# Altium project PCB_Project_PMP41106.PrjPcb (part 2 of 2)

## Sheet PCB_Project_PMP41106_CoverSheet.SchDoc
size 431 x 279 mm; Date: Not shown in title block; ApprovedBy: Not shown in title block; CheckedBy: Not shown in title block; Author: Not shown in title block; CompanyName: Not shown in title block; Engineer: Not shown in title block; Organization: Not shown in title block; Address1: Not shown in title block; Address2: Not shown in title block; Address3: Not shown in title block; Address4: Not shown in title block; DocumentNumber: 1; Revision: Use project parameter SCH_Rev; SheetNumber: 1; SheetTotal: 3; PageSetup: Record=PageOptions¦CenterHorizontal=True¦CenterVertical=True¦PrintScale=1.00¦XCorrection=1.00¦YCorrection=1.00¦PrintKind=0¦BorderSize=5000000¦LeftOffset=0¦BottomOffset=0¦Orientation=2¦PaperLength=1000¦PaperWidth=1000¦Scale=100¦PaperSource=15¦PrintQuality=600¦MediaType=1¦DitherType=10¦PaperKind=Letter¦PrintScaleMode=1
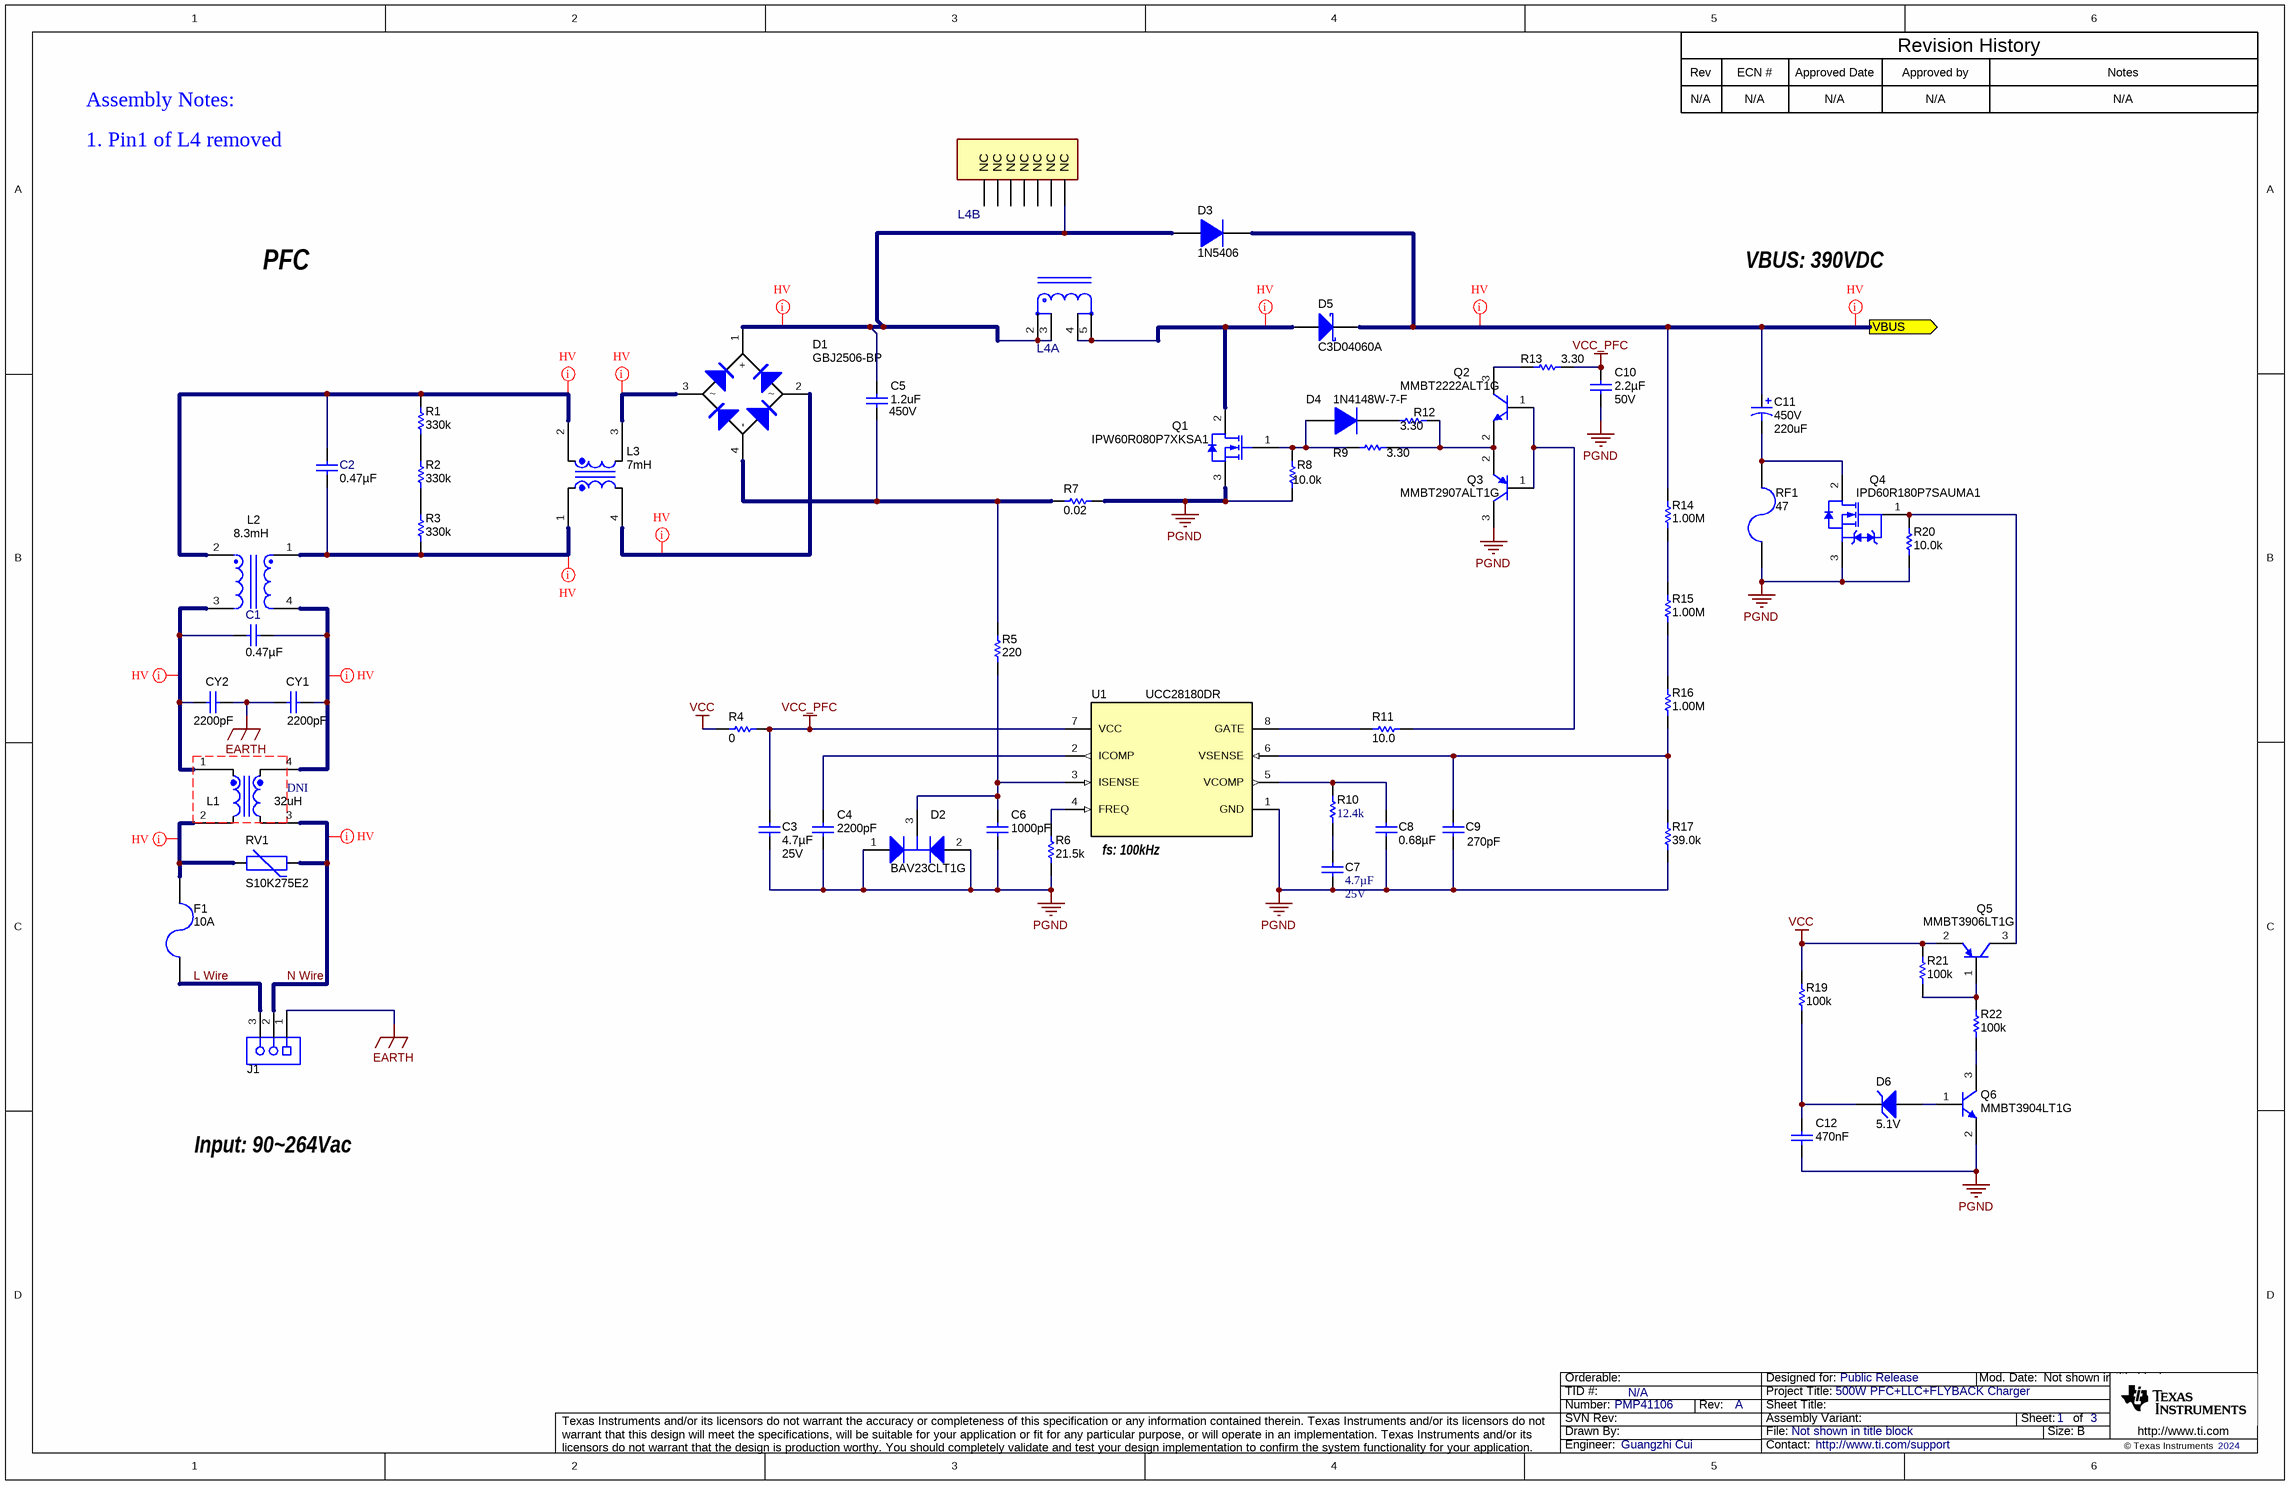
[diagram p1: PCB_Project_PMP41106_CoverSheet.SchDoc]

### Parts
C1  ValueDisplayed: 0.47µF  [Kemet_1800x850x1450]  (hidden comment: R46KI347050P0K)
C2  ValueDisplayed: 0.47µF  [Kemet_1800x850x1450]  (hidden comment: R46KI347050P0K)
C3  Cap_F: 4.7µF  VDC_V: 25V  [0805_HV]  (hidden comment: C2012X7R1E475K125AB)
C4  ValueDisplayed: 2200pF  [0603]  (hidden comment: GRM1885C1H222JA01D)
C5  VDC_V: 450V  ValueDisplayed: 1.2uF  [B32922_17.5mm]  (hidden comment: ECW-FD2W125K)
C6  ValueDisplayed: 1000pF  [0603]  (hidden comment: GRM1885C1H102FA01J)
C7  Cap_F: 4.7µF  VDC_V: 25V  [0805_150]  (hidden comment: 08053C225KAT2A)
C8  Cap_F: 0.68µF  [0603]  (hidden comment: C0603C105K3RACTU)
C9  ValueDisplayed: 270pF  [0603]  (hidden comment: GRM1885C1H271JA01D)
C10  Cap_F: 2.2µF  VDC_V: 50V  [0805_HV]  (hidden comment: C2012X7R1H225K125AC)
C11  VDC_V: 450V  ValueDisplayed: 220uF  [HXG_2500x4000]  (hidden comment: 450HXG220MEFCSN25X40)
C12  Cap_F: 470nF  [0603]  (hidden comment: GRM188R71E474KA12D)
CY1  ValueDisplayed: 2200pF  [E_900x700x900]  (hidden comment: DE6E3KJ222MN3A)
CY2  ValueDisplayed: 2200pF  [E_900x700x900]  (hidden comment: DE6E3KJ222MN3A)
D1  GBJ2506-BP  [GBJ]
D2  BAV23CLT1G  [SOT-23]
D3  1N5406  [DO-201AD]
D4  1N4148W-7-F  [SOD-123]
D5  C3D04060A  [TO-220-F2]
D6  value 5.1V  [SOD-323]  (hidden comment: MM3Z5V1ST1G)
F1  Irating_A: 10A  [FUSE_0216]  (hidden comment: 0216010.MXEP)
J1  1714968  [Phoenix_1714968]  (value not drawn)
L1  value 32uH  [WE-CMB_NiZn_S]  (hidden comment: 744842932)
L2  Ind_H: 8.3mH  [FP-YXBCM020013007C_PTH_CHOKE_12MM5_25MM0-MFG]  (hidden comment: YXBCM020013007C)
L3  value 7mH  [WE-CMBNC_L]  (hidden comment: 7448040707)
L4  MAG-3001497  [FP-MAG-3001497_PTH12-MFG]  (value not drawn)  (parts A,B of 2)
Q1  IPW60R080P7XKSA1  [TO-247]
Q2  MMBT2222ALT1G  [SOT-23]
Q3  MMBT2907ALT1G  [SOT-23]
Q4  IPD60R180P7SAUMA1  [DPAK]
Q5  MMBT3906LT1G  [SOT-23]
Q6  MMBT3904LT1G  [SOT-23]
R1  ValueDisplayed: 330k  [1206]  (hidden comment: RC1206FR-07330KL)
R2  ValueDisplayed: 330k  [1206]  (hidden comment: RC1206FR-07330KL)
R3  ValueDisplayed: 330k  [1206]  (hidden comment: RC1206FR-07330KL)
R4  ValueDisplayed: 0  [1206]  (hidden comment: RC1206JR-070RL)
R5  ValueDisplayed: 220  [0603]  (hidden comment: RC0603FR-07220RL)
R6  ValueDisplayed: 21.5k  [0603]  (hidden comment: RC0603FR-0721K5L)
R7  ValueDisplayed: 0.02  [2512]  (hidden comment: CSRN2512FK20L0)
R8  ValueDisplayed: 10.0k  [0603]  (hidden comment: RC0603FR-0710KL)
R9  ValueDisplayed: 3.30  [1206]  (hidden comment: RC1206FR-073R3L)
R10  ValueDisplayed: 12.4k  [0603]  (hidden comment: RC0603FR-0711K5L)
R11  ValueDisplayed: 10.0  [0603]  (hidden comment: RC0603FR-0710RL)
R12  ValueDisplayed: 3.30  [1206]  (hidden comment: RC1206FR-073R3L)
R13  ValueDisplayed: 3.30  [1206]  (hidden comment: RC1206FR-073R3L)
R14  ValueDisplayed: 1.00M  [1206]  (hidden comment: RC1206FR-071ML)
R15  ValueDisplayed: 1.00M  [1206]  (hidden comment: RC1206FR-071ML)
R16  ValueDisplayed: 1.00M  [1206]  (hidden comment: RC1206FR-071ML)
R17  ValueDisplayed: 39.0k  [0603]  (hidden comment: RC0603FR-0739KL)
R19  ValueDisplayed: 100k  [0603]  (hidden comment: RC0603FR-07100KL)
R20  ValueDisplayed: 10.0k  [0603]  (hidden comment: RC0603FR-0710KL)
R21  ValueDisplayed: 100k  [0603]  (hidden comment: RC0603FR-07100KL)
R22  ValueDisplayed: 100k  [0603]  (hidden comment: RC0603FR-07100KL)
RF1  ValueDisplayed: 47  [EMC2]  (hidden comment: EMC2-47RKI)
RV1  S10K275E2  [VAR_S10K275E2]
U1  UCC28180DR  [D0008A_N]

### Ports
VBUS (out)

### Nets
EARTH: CY1.1 CY2.2 J1.1
PGND: C3.2 C4.2 C6.2 C7.2 C8.2 C9.2 C10.2 C12.2 D2.1(A) D2.2(K) Q1.3(S) Q3.3(C) Q4.3(S) Q6.2(E) R6.1 R7.2 R8.1 R17.1 R20.1 RF1.2 U1.1(GND)
VCC: Q5.2(E) R4.1 R19.2 R21.2
VCC_PFC: C3.1 C10.1 R4.2 R13.1 U1.7(VCC)
L Wire: F1.2 J1.3
N Wire: J1.2 L1.3 RV1.2
VBUS: C11.1(+) D3.1(K) D5.1(K) R14.2 ; port VBUS
NetC1_1: C1.1 CY2.1 L1.1 L2.3
NetC1_2: C1.2 CY1.2 L1.4 L2.4
NetC2_1: C2.1 L2.1 L3.1 R3.1
NetC2_2: C2.2 L2.2 L3.2 R1.2
NetC4_1: C4.1 U1.2(ICOMP)
NetC5_1: C5.1 D1.1(+) D3.2(A) L4.1(NC) L4.2 L4.3
NetC5_2: C5.2 D1.4(-) R5.2 R7.1
NetC6_1: C6.1 D2.3(C) R5.1 U1.3(ISENSE)
NetC7_1: C7.1 R10.1
NetC8_1: C8.1 R10.2 U1.5(VCOMP)
NetC9_1: C9.1 R16.1 R17.2 U1.6(VSENSE)
NetC11_2: C11.2(-) Q4.2(D) RF1.1
NetC12_1: C12.1 D6.1(K) R19.1
NetD1_2: D1.2 L3.4
NetD1_3: D1.3 L3.3
NetD4_1: D4.1(K) R12.2
NetD4_2: D4.2(A) Q1.1(G) R8.2 R9.2
NetD5_2: D5.2(A) L4.4 L4.5 Q1.2(D)
NetD6_2: D6.2(A) Q6.1(B)
NetF1_1: F1.1 L1.2 RV1.1
NetQ2_1: Q2.1(B) Q3.1(B) R11.2
NetQ2_2: Q2.2(E) Q3.2(E) R9.1 R12.1
NetQ2_3: Q2.3(C) R13.2
NetQ4_1: Q4.1(G) Q5.3(C) R20.2
NetQ5_1: Q5.1(B) R21.1 R22.2
NetQ6_3: Q6.3(C) R22.1
NetR1_1: R1.1 R2.2
NetR2_1: R2.1 R3.2
NetR6_2: R6.2 U1.4(FREQ)
NetR11_1: R11.1 U1.8(GATE)
NetR14_1: R14.1 R15.2
NetR15_1: R15.1 R16.2

Not connected (* = marked no-connect by the designer): L4 7(NC) 8(NC) 9(NC) 10(NC) 11(NC) 12(NC)

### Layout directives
net class HV: N Wire, NetC1_1, NetC1_2, NetC2_1, NetC2_2, NetC5_1, NetD1_2, NetD1_3, NetD5_2, NetF1_1, VBUS

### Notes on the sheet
- Rev
- N/A
- ECN #
- Approved Date
- Approved by
- Revision History
- Notes
- Assembly Notes:
- 1. Pin1 of L4 removed
- PFC
- VBUS: 390VDC
- (near L1) DNI
- fs: 100kHz
- Input: 90|64Vac

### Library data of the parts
C1 C2 = CMP-0078590-1: CAP, Film, 0.47 µF, X2 275 VAC, +/- 10%, TH; Manufacturer: Kemet; Cap_F: 470nF; SizeAreaWB_mm2: 210; VAC_X: 275; SizeArea_mm2: 153; AEC Qualified: N; AEC Category: Q200; Value: 0.47uF; TaMax_C: 110°C; SizeZ_mm: 14.6; TaMin_C: -40°C; SizeY_mm: 8.5; CompType: Capacitor; SizeX_mm: 18; Cap_Case: 18x8.5x14.5
C3 = CMP-0007870-2: CAP, CERM, 4.7 uF, 25 V, +/- 10%, X7R, 0805; Manufacturer: TDK; TaMin_C: -55°C; Polarized: N; SizeAreaWB_mm2: 6.75; Value1: Unknown; U/M: EA; Value: 4.7uF; TaMax_C: 125°C; SizeZ_mm: 1.45; SizeX_mm: 2; SizeY_mm: 1.25; Cap_Case: 0805; SizeArea_mm2: 2.5; AEC Category: Q200
C4 = CMP-0007198-4: CAP, CERM, 2200 pF, 50 V, +/- 5%, C0G/NP0, 0603; Manufacturer: MuRata; TaMin_C: -55°C; Polarized: N; SizeAreaWB_mm2: 4.68; Value1: Unknown; U/M: EA; Value: 2200pF; TaMax_C: 125°C; SizeZ_mm: 1; SizeX_mm: 1.6; SizeY_mm: 0.8; Value2: 50V; SizeArea_mm2: 1.28; CompType: Capacitor; Cap_F: 2.2nF; AEC Category: Q200
C5 = CMP-0012412-3: CAP, Film, 1.2 uF, 450 V, +/- 10%, TH; Manufacturer: Panasonic Electronic Components; Polarized: N; SizeAreaWB_mm2: 220; Value1: Unknown; Value: 1.2uF; TaMax_C: 110°C; SizeZ_mm: 17.5; SizeX_mm: 18; SizeY_mm: 9; SizeArea_mm2: 162; CompType: Capacitor; Cap_F: 470nF; AEC Category: Q200
C6 = CMP-0007172-4: CAP, CERM, 1000 pF, 50 V, +/- 1%, C0G/NP0, 0603; Manufacturer: MuRata; TaMin_C: -55°C; Polarized: N; SizeAreaWB_mm2: 4.68; Value1: Unknown; U/M: EA; Value: 1000pF; TaMax_C: 125°C; SizeZ_mm: 1; SizeX_mm: 1.6; SizeY_mm: 0.8; Value2: 50V; SizeArea_mm2: 1.28; CompType: Capacitor; Cap_F: 1nF; AEC Category: Q200
C7 = CMP-0007870-2: CAP, CERM, 4.7 uF, 25 V, +/- 10%, X7R, 0805; Manufacturer: TDK; PartNumber: C2012X7R1E475K125AB; TaMin_C: -55°C; Polarized: N; SizeAreaWB_mm2: 6.75; Value1: Unknown; U/M: EA; Value: 4.7uF; TaMax_C: 125°C; SizeZ_mm: 1.45; SizeX_mm: 2; SizeY_mm: 1.25; Cap_Case: 0805; SizeArea_mm2: 2.5; AEC Category: Q200
C8 = CMP-0006867-4: CAP, CERM, 0.68uF, 25 V, +/- 10%, X7R, 0603; Manufacturer: Kemet; TaMin_C: -55°C; Polarized: N; SizeAreaWB_mm2: 4.68; Value1: Unknown; U/M: EA; TaMax_C: 125°C; SizeZ_mm: 1; SizeX_mm: 1.6; SizeY_mm: 0.8; Value2: 25V; SizeArea_mm2: 1.28; CompType: Capacitor; AEC Category: Q200; ValueDisplayed: 1uF
C9 = CMP-0007203-4: CAP, CERM, 270 pF, 50 V, +/- 5%, C0G/NP0, 0603; Manufacturer: MuRata; TaMin_C: -55°C; Polarized: N; SizeAreaWB_mm2: 4.68; Value1: Unknown; U/M: EA; Value: 270pF; TaMax_C: 125°C; SizeZ_mm: 1; SizeX_mm: 1.6; SizeY_mm: 0.8; Value2: 50V; SizeArea_mm2: 1.28; CompType: Capacitor; AEC Category: Q200
C10 = CMP-0007877-2: CAP, CERM, 2.2 uF, 50 V, +/- 10%, X7R, 0805; Manufacturer: TDK; TaMin_C: -55°C; ESR_ohm: 3.66m; Polarized: N; SizeAreaWB_mm2: 6.75; Value1: 0.00366 ohm; U/M: EA; Value: 2.2uF; TaMax_C: 125°C; SizeZ_mm: 1.45; SizeX_mm: 2; SizeY_mm: 1.25; Cap_Case: 0805; SizeArea_mm2: 2.5; IRMS_A: 3.41207A; AEC Category: Q200
C11 = CMP-0009979-2: CAP, AL, 220 uF, 450 V, +/- 20%, TH; Manufacturer: Rubycon; TaMin_C: -25°C; Polarized: Y; SizeAreaWB_mm2: 729; Value1: Unknown; U/M: EA; Value: 220uF; TaMax_C: 105°C; SizeZ_mm: 42; SizeX_mm: 25; Cap_Case: 25x40mm; SizeArea_mm2: 625; CompType: Capacitor; AEC Qualified: N; Cap_F: 220µF; IRMS_A: 1.97A; AEC Category: Q200
C12 = CMP-0007424-4: CAP, CERM, 0.47 uF, 25 V, +/- 10%, X7R, 0603; Manufacturer: MuRata; TaMin_C: -55°C; Polarized: N; SizeAreaWB_mm2: 4.68; Value1: Unknown; U/M: EA; Value: 0.47uF; TaMax_C: 125°C; SizeZ_mm: 1; SizeX_mm: 1.6; SizeY_mm: 0.8; Value2: 25V; SizeArea_mm2: 1.28; CompType: Capacitor; AEC Category: Q200
CY1 CY2 = DE6E3KJ222MN3A: CAP, CERM, 2200 pF, 300 V, +/- 20%, E, TH, 2- Leads, Body 9x7mm, Pin Spacing 7.5mm; Manufacturer: MuRata; Polarized: N; CompType: Capacitor; Value: 2200pF; U/M: EA; Cap_F: 0.0000000022; Tolerance_%: 20; Value1: Unknown; VDC_V: 300; Value2: 300V; TaMin_C: -40; TaMax_C: 125; Cap_Case: 9x7x9mm; SizeArea_mm2: 63; SizeAreaWB_mm2: 99; SizeX_mm: 9; SizeY_mm: 7; SizeZ_mm: 12; AEC Category: Q200
D1 = CMP-0082068-2: Diode, P-N-Bridge, 600 V, 25 A, TH; Manufacturer: Micro Commercial Components; AEC Category: Q101; Io_A: 25A; SizeY_mm: 4.6; AEC Qualified: N; SizeZ_mm: 24; Vr_V: 600V; SizeAreaWB_mm2: 211.2; Value: 600V; SizeX_mm: 30; TJmax_C: 150°C; Vf_V: 1.05V; RJC_CperW: 0.6; SizeArea_mm2: 138
D2 = CMP-0029178-2: Diode, Switching, 250 V, 0.4 A, SOT-23; Manufacturer: ON Semiconductor; Value2: 1.25V; SizeArea_mm2: 7.5; SizeAreaWB_mm2: 14; Green_Lifecycle: Not Set; Green_REACh: Incomplete; Io_A: 4dA; Vr_V: 250V; SizeZ_mm: 1.1; Value1: 0.4A; Value: 250V; SizeY_mm: 3; SizeX_mm: 2.5; TJmax_C: 150°C; AEC Category: Q101; AEC Qualified: N
D3 = CMP-0029223-3: Diode, Switching-Bridge, 600 V, 3 A, TH; Manufacturer: Vishay-Semiconductor; SizeArea_mm2: 109.08; Value1: 3A; Green_Lifecycle: Not Set; Green_REACh: Incomplete; AEC Category: Q101; Vr_V: 600V; Value: 600V; Value2: 1.2V; SizeAreaWB_mm2: 166.38; SizeX_mm: 21.6; SizeY_mm: 5.05; TJmax_C: 150°C; SizeZ_mm: 5.3
D4 = CMP-0029001-2: Diode, Ultrafast, 100 V, 0.15 A, SOD-123; Manufacturer: Diodes Inc.; SizeX_mm: 3.85; Value2: 1.25V; Green_REACh: Passed; TJmax_C: 150°C; AEC Category: Q101; SizeAreaWB_mm2: 13.095; Value: 100V; Green_Lifecycle: Active; SizeY_mm: 1.7; Value1: 0.15A; SizeArea_mm2: 6.545; Io_A: 1.5dA; SizeZ_mm: 1.35
D5 = CMP-0028618-2: Diode, Schottky, 600 V, 4 A, TH; Manufacturer: Cree; Green_Lifecycle: Active; Io_A: 4A; RJC_CperW: 11.5; SizeZ_mm: 19.431; Value: 600V; SizeY_mm: 4.445; Value2: 1.8V; SizeX_mm: 10.045; SizeAreaWB_mm2: 77.630025; TJmax_C: 175°C; AEC Category: Q101; SizeArea_mm2: 44.650025; Green_REACh: Passed
D6 = CMP-0085739-1: Diode, Zener, 5.1 V, 300 mW, SOD-323; Manufacturer: ON Semiconductor; RJA_CperW: 416; Power_W: 300mW; SizeZ_mm: 1; AEC Qualified: N; SizeAreaWB_mm2: 8.695; SizeArea_mm2: 3.645; SizeX_mm: 2.7; SizeY_mm: 1.35; AEC Category: Q101; Value1: 0.3W
F1 = CMP-0079917-2: Fuse, 10 A, 250 VAC, TH; PartNumber: 0216008.MXEP; Manufacturer: Littelfuse; VAC_V: 250V; Rtyp_Ohm: 0.0123; MeltingTyp: 64.315; Interrupt_AC: 1.5kA
J1 = CMP-0055483-1: Terminal Block, 3x1, 6.35 mm, TH; Manufacturer: Phoenix Contact; CT: TRUE; CNHeader: FALSE
L1 = CMP-0013095-2: Coupled inductor, 8.5 A, 0.0055 ohm, TH; Manufacturer: Wurth Elektronik; DCR_ohm: 0.0055
L2 = CMP-0089807-1: 8.3mH @ 10kHz 2 Line Common Mode Choke Through Hole DCR 12mOhm; Manufacturer: YAXIN ELECTRONICS; SizeZ_mm: 23.5mm; DCR_ohm: 0.012; AEC Qualified: No; Tolerance_%: 30%
L3 = CMP-0013082-2: Coupled inductor, 7 mH, 7 A, 0.02 ohm, TH; Manufacturer: Wurth Elektronik; DCR_ohm: 0.02
L4 = CMP-0120779-1: PFC INDUCTOR; Manufacturer: Bourns; AEC Qualified: No; DCR_ohm: 0.142; Ind_H: 340µH; SizeZ_mm: 34mm; Value: 340uH; Test Frequency: 100kHz; Tolerance_%: 10%
Q1 = CMP-0001178-3: MOSFET, N-CH, 600 V, 37 A, TO-247; Alternate Manufacturer: None; Manufacturer: Infineon Technologies; SizeZ_mm: 25; ChType: N; Value2: 51 nC; VdsMax_V: 600V; SizeX_mm: 15.6; SizeY_mm: 5; Vgs_V: 20V; QgTyp_nC: 51; Value: 600V; SizeArea_mm2: 78; AEC Category: Q101; IdsMax_A: 53A; SizeAreaWB_mm2: 123.2; ChMode: Enhancement
Q2 = CMP-0000461-2: Transistor, NPN, 40 V, 0.6 A, SOT-23; Manufacturer: ON Semiconductor; TaMax_C: 150°C; Value1: 0.6 A; Vcesat1_V: 1V; SizeX_mm: 2.5; SizeY_mm: 3; TaMin_C: -55°C; IcRated_A: 6dA; CompType: BJT; SizeZ_mm: 1.1; Value: 40 V; SizeArea_mm2: 7.5; NPN: 1; Vceo_V: 40V; PNP: 0; AEC Category: Q101; SizeAreaWB_mm2: 14; U/M: EA
Q3 = CMP-0000344-2: Transistor, PNP, 60 V, 0.6 A, SOT-23; Manufacturer: ON Semiconductor; TaMax_C: 150°C; Value1: 0.6 A; Vcesat1_V: 1.6V; SizeX_mm: 2.5; SizeY_mm: 3; TaMin_C: -55°C; IcRated_A: 6dA; CompType: BJT; SizeZ_mm: 1.1; Value: 60 V; SizeArea_mm2: 7.5; NPN: 0; Vceo_V: 60V; PNP: 1; AEC Category: Q101; SizeAreaWB_mm2: 14; U/M: EA
Q4 = CMP-0079238-2: MOSFET, N-CH, 600 V, 18 A, DPAK; Alternate Manufacturer: None; Manufacturer: Infineon Technologies; ChType: N; Vgs_V: 20V; ChMode: Enhancement; Value1: 180m ohm; SizeAreaWB_mm2: 101.7114; SizeZ_mm: 2.29; QgTyp_nC: 25; VdsMax_V: 600V; SizeArea_mm2: 64.8114; SizeY_mm: 6.54; AEC Category: Q101; Value: 600V; SizeX_mm: 9.91; IdsMax_A: 12A; Value2: 25 nC
Q5 = CMP-0000325-2: Transistor, PNP, 40 V, 0.2 A, SOT-23; Manufacturer: ON Semiconductor; TaMax_C: 150°C; Value2: 300; Value1: 0.2 A; Vcesat1_V: 2.5dV; SizeX_mm: 2.5; SizeY_mm: 3; TaMin_C: -55°C; IcRated_A: 2dA; CompType: BJT; SizeZ_mm: 1.1; Value: 40 V; SizeArea_mm2: 7.5; NPN: 0; Vceo_V: 40V; PNP: 1; AEC Category: Q101; SizeAreaWB_mm2: 14; U/M: EA
Q6 = CMP-0000419-2: Transistor, NPN, 40 V, 0.2 A, SOT-23; Manufacturer: ON Semiconductor; TaMax_C: 150°C; Value2: 300; Value1: 0.2 A; Vcesat1_V: 3dV; SizeX_mm: 2.5; SizeY_mm: 3; TaMin_C: -55°C; IcRated_A: 2dA; CompType: BJT; SizeZ_mm: 1.1; Value: 40 V; SizeArea_mm2: 7.5; NPN: 1; Vceo_V: 40V; PNP: 0; AEC Category: Q101; SizeAreaWB_mm2: 14; U/M: EA
R1-R3 = CMP-0018205-2: RES, 330 k, 1%, 0.25 W, 1206; Manufacturer: Yageo America; Power_W: 250mW; TempCo: 100 ppm/C; U/M: EA; Value: 330k; SizeX_mm: 3.2; SizeY_mm: 1.6; SizeZ_mm: 1.35; Value2: 0.25W; SizeArea_mm2: 5.12; VDC_V: 200V; AEC Category: Q200
R4 = CMP-0018759-2: RES, 0, 5%, 0.25 W, 1206; Manufacturer: Yageo America; Power_W: 250mW; TempCo: 200 ppm/C; Value_Code: 0000; U/M: EA; Value: 0; EIA_Code: E24; SizeX_mm: 3.2; SizeY_mm: 1.6; SizeZ_mm: 1.35; Value2: 0.25W; SizeArea_mm2: 5.12; VDC_V: 200V; AEC Category: Q200
R5 = CMP-0022918-5: RES, 220, 1%, 0.1 W, 0603; Manufacturer: Yageo; Power_W: 100mW; TempCo: 100 ppm/C; Value_Code: 220R; Value: 220; SizeX_mm: 1.6; SizeY_mm: 0.8; SizeZ_mm: 1; Value2: 0.1W; SizeArea_mm2: 1.28; AEC Qualified: N; VDC_V: 75V; AEC Category: Q200; SizeAreaWB_mm2: 4.68
R6 = CMP-0022913-5: RES, 21.5 k, 1%, 0.1 W, 0603; Manufacturer: Yageo; Power_W: 100mW; TempCo: 100 ppm/C; Value_Code: 21k5; Value: 21.5k; EIA_Code: E96; SizeX_mm: 1.6; SizeY_mm: 0.8; SizeZ_mm: 1; Value2: 0.1W; SizeArea_mm2: 1.28; AEC Qualified: N; VDC_V: 75V; AEC Category: Q200; SizeAreaWB_mm2: 4.68
R7 = CMP-0015773-2: RES, 0.02, 1%, 2 W, 2512; Manufacturer: Stackpole Electronics Inc; Power_W: 2W; TempCo: 200 ppm/C; Value_Code: R020; U/M: EA; Value: 0.02; EIA_Code: E96; SizeX_mm: 6.3; SizeY_mm: 3.2; SizeZ_mm: 0.71; SizeArea_mm2: 20.16; AEC Category: Q200
R8 R20 = CMP-0022746-5: RES, 10.0 k, 1%, 0.1 W, 0603; Manufacturer: Yageo; Power_W: 100mW; TempCo: 100 ppm/C; Value_Code: 10k0; Value: 10.0k; EIA_Code: E96; Res_ohm: 10k; SizeX_mm: 1.6; SizeY_mm: 0.8; SizeZ_mm: 1; Value2: 0.1W; SizeArea_mm2: 1.28; AEC Qualified: N; VDC_V: 75V; AEC Category: Q200; SizeAreaWB_mm2: 4.68
R9 R12 R13 = CMP-0018270-2: RES, 3.30, 1%, 0.25 W, 1206; Manufacturer: Yageo America; Power_W: 250mW; TempCo: 200 ppm/C; Value_Code: 3R30; U/M: EA; Value: 3.30; Res_ohm: 3.3; SizeX_mm: 3.2; SizeY_mm: 1.6; SizeZ_mm: 1.35; Value2: 0.25W; SizeArea_mm2: 5.12; VDC_V: 200V; AEC Category: Q200
R10 = CMP-0086298-1: RES, 12.4 k, 1%, 0.1 W, AEC-Q200 Grade 0, 0603; PartNumber: ERJ-3EKF1242V; Manufacturer: Panasonic; SizeY_mm: 0.8; SizeZ_mm: 1; AEC Grade: 0; Value: 12.4k; Value_Code: 12k4; SizeArea_mm2: 1.28; TempCo: 100 ppm/C; SizeX_mm: 1.6; AEC Qualified: Y; Power_W: 100mW; SizeAreaWB_mm2: 4.68; EIA_Code: E96; AEC Category: Q200; Value2: 0.1W
R11 = CMP-0022751-4: RES, 10.0, 1%, 0.1 W, 0603; Manufacturer: Yageo; Power_W: 100mW; TempCo: 100 ppm/C; Value_Code: 10R0; Value: 10.0; EIA_Code: E96; Res_ohm: 10; SizeX_mm: 1.6; SizeY_mm: 0.8; SizeZ_mm: 1; Value2: 0.1W; SizeArea_mm2: 1.28; AEC Qualified: N; VDC_V: 75V; AEC Category: Q200; SizeAreaWB_mm2: 4.68
R14-R16 = CMP-0018027-2: RES, 1.00 M, 1%, 0.25 W, 1206; Manufacturer: Yageo America; Power_W: 250mW; TempCo: 100 ppm/C; Value_Code: 1M00; U/M: EA; Value: 1.00Meg; EIA_Code: E96; Res_ohm: 1M; SizeX_mm: 3.2; SizeY_mm: 1.6; SizeZ_mm: 1.35; Value2: 0.25W; SizeArea_mm2: 5.12; VDC_V: 200V; AEC Category: Q200
R17 = CMP-0023073-5: RES, 39.0 k, 1%, 0.1 W, 0603; Manufacturer: Yageo; Power_W: 100mW; TempCo: 100 ppm/C; Value_Code: 39k0; Value: 39.0k; Res_ohm: 39k; SizeX_mm: 1.6; SizeY_mm: 0.8; SizeZ_mm: 1; Value2: 0.1W; SizeArea_mm2: 1.28; AEC Qualified: N; VDC_V: 75V; AEC Category: Q200; SizeAreaWB_mm2: 4.68
R19 R21 R22 = CMP-0022735-5: RES, 100 k, 1%, 0.1 W, 0603; Manufacturer: Yageo; Power_W: 100mW; TempCo: 100 ppm/C; Value: 100k; EIA_Code: E96; SizeX_mm: 1.6; SizeY_mm: 0.8; SizeZ_mm: 1; Value2: 0.1W; SizeArea_mm2: 1.28; AEC Qualified: N; VDC_V: 75V; AEC Category: Q200; SizeAreaWB_mm2: 4.68
RF1 = CMP-0014288-1: RES, 47, 10%, 2 W, Axial resistor; Manufacturer: TT Electronics/IRC; Power_W: 2W; TempCo: 100 ppm/C; Value_Code: 47R0; U/M: EA; Value: 47; CompType: Fusible Resistor; AEC Category: Q200
RV1 = CMP-0002100-2: Varistor 275V RMS 10MM Radial, TH; Manufacturer: TDK; SizeZ_mm: 14.5; SizeX_mm: 12; SizeY_mm: 5.4; SizeAreaWB_mm2: 103.6; SizeArea_mm2: 64.8
U1 = CMP-0074100-1: 8-PIN CONTINUOUS CONDUCTION MODE (CCM) PFC CONTROLLER, D0008A (SOIC-8); Alternate Manufacturer: Texas Instruments; SizeAreaWB_mm2: 56.58; U/M: EA; SizeZ_mm: 1.75; SizeX_mm: 4.9; SizeY_mm: 6.2; SizeArea_mm2: 30.38; CompType: IC

## Sheet PCB_Project_PMP41106_EVM_Hardware.SchDoc
size 431 x 279 mm; Date: Not shown in title block; ApprovedBy: Not shown in title block; CheckedBy: Not shown in title block; Author: Not shown in title block; CompanyName: Not shown in title block; Engineer: Not shown in title block; Organization: Not shown in title block; Address1: Not shown in title block; Address2: Not shown in title block; Address3: Not shown in title block; Address4: Not shown in title block; DocumentNumber: 1; Revision: Use project parameter SCH_Rev; SheetNumber: 3; SheetTotal: 3; PageSetup: Record=PageOptions¦CenterHorizontal=True¦CenterVertical=True¦PrintScale=1.00¦XCorrection=1.00¦YCorrection=1.00¦PrintKind=0¦BorderSize=5000000¦LeftOffset=0¦BottomOffset=0¦Orientation=2¦PaperLength=1000¦PaperWidth=1000¦Scale=100¦PaperSource=15¦PrintQuality=600¦MediaType=1¦DitherType=10¦PaperKind=Letter¦PrintScaleMode=1
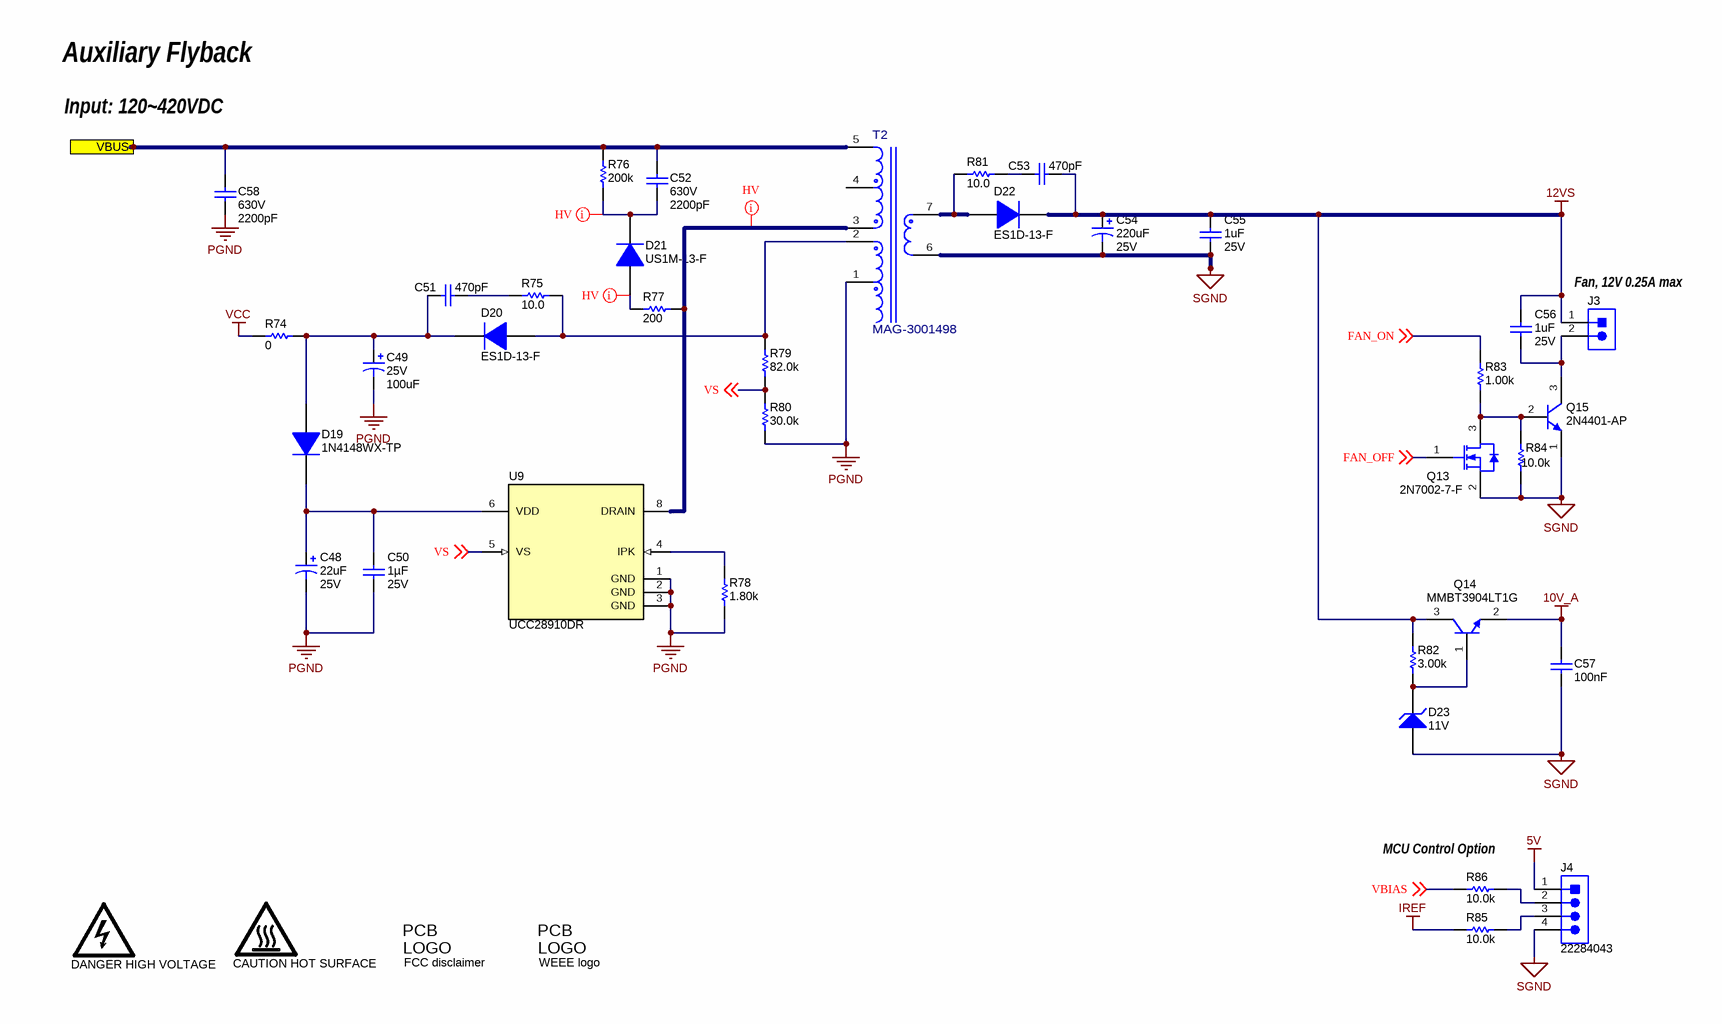
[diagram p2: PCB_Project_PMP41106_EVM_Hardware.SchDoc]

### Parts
C48  VDC_V: 25V  ValueDisplayed: 22uF  [ML_500x500]  (hidden comment: 25ML22MEFC5X5)
C49  VDC_V: 25V  ValueDisplayed: 100uF  [FM_630x1120]  (hidden comment: EEU-FM1E101)
C50  VDC_V: 25V  Cap_F: 1µF  [0603]  (hidden comment: C1608X7R1E105K080AE)
C51  ValueDisplayed: 470pF  [0805_HV]  (hidden comment: 08051A471JAT2A)
C52  VDC_V: 630V  ValueDisplayed: 2200pF  [1206]  (hidden comment: GRM31BR72J222KW01L)
C53  ValueDisplayed: 470pF  [0805_HV]  (hidden comment: 08051A471JAT2A)
C54  VDC_V: 25V  ValueDisplayed: 220uF  [Chemi-Con_800x1150]  (hidden comment: EKZE250ELL221MHB5D)
C55  VDC_V: 25V  ValueDisplayed: 1uF  [0805_HV]  (hidden comment: GRM216R61E105KA12D)
C56  VDC_V: 25V  ValueDisplayed: 1uF  [0805_HV]  (hidden comment: GRM216R61E105KA12D)
C57  Cap_F: 100nF  [0603]  (hidden comment: C0603X104K3RACTU)
C58  VDC_V: 630V  ValueDisplayed: 2200pF  [1206]  (hidden comment: GRM31BR72J222KW01L)
D19  1N4148WX-TP  [SOD-323]
D20  ES1D-13-F  [SMA]
D21  US1M-13-F  [SMA]
D22  ES1D-13-F  [SMA]
D23  value 11V  [SOD-323]  (hidden comment: BZX384-C11,115)
J3  705430001  [Molex_0705430001]  (value not drawn)
J4  22284043  [Molex_0022284043]
LOGO1  DANGER HIGH VOLTAGE  [IEC_HighVoltage_Small]  (no BOM)
LOGO2  CAUTION HOT SURFACE  [IEC_HotSurface_Small]  (no BOM)
Logo3  FCC disclaimer  [FCC_disclaimer]  (no BOM)
Logo4  WEEE logo  [WEEE_Minimum]  (no BOM)
Q13  2N7002-7-F  [SOT-23]
Q14  MMBT3904LT1G  [SOT-23]
Q15  2N4401-AP  [TO-92AP]
R74  ValueDisplayed: 0  [1206]  (hidden comment: RC1206JR-070RL)
R75  ValueDisplayed: 10.0  [1206]  (hidden comment: RC1206FR-0710RL)
R76  ValueDisplayed: 200k  [1206]  (hidden comment: RC1206FR-07200KL)
R77  ValueDisplayed: 200  [1206]  (hidden comment: RC1206FR-07200RL)
R78  ValueDisplayed: 1.80k  [0603]  (hidden comment: RC0603FR-071K8L)
R79  ValueDisplayed: 82.0k  [0603]  (hidden comment: RC0603FR-0782KL)
R80  ValueDisplayed: 30.0k  [0603]  (hidden comment: RC0603FR-0730KL)
R81  ValueDisplayed: 10.0  [1206]  (hidden comment: RC1206FR-0710RL)
R82  ValueDisplayed: 3.00k  [0603]  (hidden comment: RC0603FR-073KL)
R83  ValueDisplayed: 1.00k  [0603]  (hidden comment: RC0603FR-071KL)
R84  ValueDisplayed: 10.0k  [0603]  (hidden comment: RC0603FR-0710KL)
R85  ValueDisplayed: 10.0k  [1206]  (hidden comment: RC1206FR-0710KL)
R86  ValueDisplayed: 10.0k  [0603]  (hidden comment: RC0603FR-0710KL)
T2  MAG-3001498  [FP-MAG-3001498_PTH_XFRMR_20MM5_14MM2-MFG]
U9  UCC28910DR  [D0007A_N]

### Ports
VBUS (in)

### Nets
5V: J4.1
10V_A: C57.1 Q14.2(E)
12VS: C53.1 C54.1(+) C55.1 C56.1 D22.1(K) J3.1 Q14.3(C) R82.1
IREF: R85.1
PGND: C48.2(-) C49.2(-) C50.2 C58.2 R78.1 R80.1 T2.1 U9.1(GND) U9.2(GND) U9.3(GND)
SGND: C54.2(-) C55.2 C57.2 D23.2(A) J4.4 Q13.2(S) Q15.1(E) R84.1 T2.6
VCC: R74.1
FAN_OFF: Q13.1(G) ; off-sheet FAN_OFF
FAN_ON: R83.2 ; off-sheet FAN_ON
VBIAS: R86.2 ; off-sheet VBIAS
VBUS: C52.1 C58.1 R76.2 T2.5 ; port VBUS
VS: R79.1 R80.2 U9.5(VS) ; off-sheet VS
NetC48_1: C48.1(+) C50.1 D19.1(K) U9.6(VDD)
NetC49_1: C49.1(+) C51.2 D19.2(A) D20.1(K) R74.2
NetC51_1: C51.1 R75.1
NetC52_2: C52.2 D21.1(K) R76.1
NetC53_2: C53.2 R81.2
NetC56_2: C56.2 J3.2 Q15.3(C)
NetD20_2: D20.2(A) R75.2 R79.2 T2.2
NetD21_2: D21.2(A) R77.2
NetD22_2: D22.2(A) R81.1 T2.7
NetD23_1: D23.1(K) Q14.1(B) R82.2
NetJ4_2: J4.2 R86.1
NetJ4_3: J4.3 R85.2
NetQ13_3: Q13.3(D) Q15.2(B) R83.1 R84.2
NetR77_1: R77.1 T2.3 U9.8(DRAIN)
NetR78_2: R78.2 U9.4(IPK)

Not connected (* = marked no-connect by the designer): T2 4

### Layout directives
net class HV: NetC52_2, NetD21_2, NetR77_1

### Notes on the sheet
- Auxiliary Flyback
- Input: 120~420VDC
- (near J3) Fan, 12V 0.25A max
- (near R86) MCU Control Option

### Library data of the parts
C48 = CMP-0010292-1: CAP, AL, 22 uF, 25 V, +/- 20%, TH; Manufacturer: Rubycon; TaMin_C: -40°C; Polarized: Y; SizeAreaWB_mm2: 49; Value1: Unknown; U/M: EA; Value: 22uF; TaMax_C: 105°C; SizeZ_mm: 6.5; SizeX_mm: 5; Cap_Case: 5x5; SizeArea_mm2: 25; CompType: Capacitor; Cap_F: 22µF; IRMS_A: 42mA; AEC Category: Q200
C49 = CMP-0010339-1: CAP, AL, 100 uF, 25 V, +/- 20%, 0.13 ohm, TH; Manufacturer: Panasonic; TaMin_C: -40°C; ESR_ohm: 1.3d; Polarized: Y; SizeAreaWB_mm2: 68.89; U/M: EA; Value: 100uF; TaMax_C: 105°C; SizeZ_mm: 12.7; SizeX_mm: 6.3; Cap_Case: 6.3x11.2; SizeArea_mm2: 39.69; CompType: Capacitor; AEC Qualified: N; Cap_F: 100µF; IRMS_A: 4.55dA; AEC Category: Q200
C50 = CMP-0860549-1: CAP, CERM, 1 µF, 25 V,+/- 10%, X7R, 0603; Manufacturer: TDK; SizeZ_mm: 1; AEC Qualified: N; SizeX_mm: 1.6; TaMin_C: -55°C; U/M: EA; SizeY_mm: 0.8; SizeAreaWB_mm2: 4.68; AEC Category: Q200; SizeArea_mm2: 1.28; Value: 1uF; TaMax_C: 125°C
C51 C53 = CMP-0007534-2: CAP, CERM, 470 pF, 100 V, +/- 5%, C0G/NP0, 0805; Manufacturer: AVX; TaMin_C: -55°C; ESR_ohm: 1.59d; Polarized: N; SizeAreaWB_mm2: 6.75; Value1: 0.159 ohm; U/M: EA; Value: 470pF; TaMax_C: 125°C; SizeZ_mm: 1.45; SizeX_mm: 2; SizeY_mm: 1.25; Cap_Case: 0805; Value2: 100V; SizeArea_mm2: 2.5; CompType: Capacitor; AEC Category: Q200
C52 C58 = CMP-0008912-2: CAP, CERM, 2200 pF, 630 V, +/- 10%, X7R, 1206; Manufacturer: MuRata; TaMin_C: -55°C; Polarized: N; SizeAreaWB_mm2: 10.92; Value1: Unknown; U/M: EA; Value: 2200pF; TaMax_C: 125°C; SizeZ_mm: 1.35; SizeX_mm: 3.2; SizeY_mm: 1.6; SizeArea_mm2: 5.12; Cap_F: 2.2nF; AEC Category: Q200
C54 = CMP-0010404-1: CAP, AL, 220 uF, 25 V, +/- 20%, TH; Manufacturer: Chemi-Con; TaMin_C: -40°C; Polarized: Y; SizeAreaWB_mm2: 100; Value1: Unknown; U/M: EA; Value: 220uF; TaMax_C: 105°C; SizeZ_mm: 13; SizeX_mm: 8; Cap_Case: 8x11.5; SizeArea_mm2: 64; CompType: Capacitor; AEC Qualified: N; Cap_F: 220µF; IRMS_A: 7.6dA; AEC Category: Q200
C55 C56 = CMP-0008136-2: CAP, CERM, 1 uF, 25 V, +/- 10%, X5R, 0805; Manufacturer: MuRata; TaMin_C: -55°C; ESR_ohm: 9m; Polarized: N; SizeAreaWB_mm2: 6.75; Value1: 0.009 ohm; U/M: EA; Value: 1uF; TaMax_C: 85°C; SizeZ_mm: 1.45; SizeX_mm: 2; SizeY_mm: 1.25; Cap_Case: 0805; SizeArea_mm2: 2.5; Cap_F: 1µF; AEC Category: Q200
C57 = CMP-0006979-5: CAP, CERM, 0.1 uF, 25 V, +/- 10%, X7R, 0603; Manufacturer: Kemet; TaMin_C: -55°C; Polarized: N; SizeAreaWB_mm2: 4.68; Value1: Unknown; U/M: EA; Value: 0.1uF; TaMax_C: 125°C; SizeZ_mm: 1; SizeX_mm: 1.6; SizeY_mm: 0.8; Value2: 25V; SizeArea_mm2: 1.28; CompType: Capacitor; AEC Category: Q200
D19 = CMP-0082069-2: Diode, Switching, 75 V, 0.15 A, SOD-323; Manufacturer: Micro Commercial Components; AEC Category: Q101; AEC Qualified: N; Value1: 0.15A; SizeX_mm: 2.7; Vr_V: 75V; Vf_V: 1V; SizeZ_mm: 1; SizeY_mm: 1.35; Value: 75V; SizeAreaWB_mm2: 8.695; TJmax_C: 150°C; RJC_CperW: 625; Io_A: 1.5dA; SizeArea_mm2: 3.645
D20 D22 = CMP-0029024-2: Diode, Ultrafast, 200 V, 1 A, SMA; Manufacturer: Diodes Inc.; Value2: 0.92V; Green_Lifecycle: Active; Io_A: 1A; Vf_V: 9.2dV; Value: 200V; SizeX_mm: 5.59; AEC Category: Q101; TJmax_C: 150°C; SizeAreaWB_mm2: 37.3428; SizeArea_mm2: 16.3228; RJC_CperW: 25; SizeZ_mm: 2.87; Green_REACh: Passed; SizeY_mm: 2.92
D21 = CMP-0076882-2: Diode, Ultrafast, 1000 V, 1 A, SMA; Manufacturer: Diodes Inc.; AEC Category: Q101; Value2: 1.7V; SizeZ_mm: 2.87; Green_REACh: Incomplete; Value: 1000V; Value1: 1A; SizeAreaWB_mm2: 37.3428; Green_Lifecycle: Not Set; RJC_CperW: 30.0; SizeX_mm: 5.59; SizeArea_mm2: 16.3228; Vr_V: 1kV; TJmax_C: 150°C; SizeY_mm: 2.92
D23 = CMP-0005842-4: Diode, Zener, 11 V, 300 mW, SOD-323; Manufacturer: NXP Semiconductor; Power_W: 300mW; SizeArea_mm2: 3.645; RJA_CperW: 415; AEC Category: Q101; Value1: 0.3W; SizeY_mm: 1.35; SizeZ_mm: 1; SizeX_mm: 2.7; SizeAreaWB_mm2: 8.695
J3 = CMP-0055242-1: Header(shrouded), 2.54mm, 2x1, Gold, TH; Manufacturer: Molex; CNHeader: FALSE; Current_A: 3A; Shrouded: Y; Gender: Male; Voltage_V: 250V; Row_Count: 1
J4 = CMP-0055331-1: Header, 2.54mm, 4x1, Tin, TH; Manufacturer: Molex; CNHeader: TRUE; Current_A: 4A; Shrouded: N; Gender: Male; Voltage_V: 250V; Row_Count: 1; Pitch_mm: 2.54; CT: FALSE; Cert_UL: Y
LOGO1 = CMP-0074835-1: IEC 61010-1 High Voltage Warning; Library Reference: IEC_HighVoltage; SymbolCreator: a0412235
LOGO2 = CMP-0074837-1: IEC 61010-1 Hot Surface Warning; Library Reference: IEC_HotSurface; SymbolCreator: a0412235
Logo3 = CMP-0074847-1: FCC_disclaimer; Library Reference: Logo
Logo4 = CMP-0074769-1
Q13 = CMP-0000769-1: MOSFET, N-CH, 60 V, 0.17 A, SOT-23; Alternate Manufacturer: None; Manufacturer: Diodes Inc.; SizeZ_mm: 1.1; ChType: N; Value2: 223 nC; Value1: 7; VdsMax_V: 60V; SizeX_mm: 2.5; SizeY_mm: 3; Vgs_V: 20V; Value: 60V; Rdson45_ohm: 7.5; AEC Category: Q101; IdsMax_A: 1.7dA; SizeAreaWB_mm2: 14; U/M: EA; QgTyp_nC: 223
Q14 = CMP-0000419-2: as Q6 on sheet PCB_Project_PMP41106_CoverSheet
Q15 = CMP-0000425-2: Transistor, NPN, 40 V, 0.5 A, TO-92AP; Manufacturer: Micro Commercial Components; TaMax_C: 150°C; Value2: 300; Value1: 0.5 A; Vcesat1_V: 7.5dV; SizeX_mm: 5.08; SizeY_mm: 3.8; TaMin_C: -55°C; IcRated_A: 5dA; CompType: BJT; SizeZ_mm: 8.5; Value: 40 V; SizeArea_mm2: 19.304; NPN: 1; Vceo_V: 40V; PNP: 0; AEC Category: Q101; SizeAreaWB_mm2: 41.064; U/M: EA
R74 = CMP-0018759-2: as R4 on sheet PCB_Project_PMP41106_CoverSheet
R75 R81 = CMP-0017851-2: RES, 10.0, 1%, 0.25 W, 1206; Manufacturer: Yageo America; Power_W: 250mW; TempCo: 200 ppm/C; Value_Code: 10R0; U/M: EA; Value: 10.0; EIA_Code: E96; Res_ohm: 10; SizeX_mm: 3.2; SizeY_mm: 1.6; SizeZ_mm: 1.35; Value2: 0.25W; SizeArea_mm2: 5.12; VDC_V: 200V; AEC Category: Q200
R76 = CMP-0018060-2: RES, 200 k, 1%, 0.25 W, 1206; Manufacturer: Yageo America; Power_W: 250mW; TempCo: 100 ppm/C; U/M: EA; Value: 200k; EIA_Code: E96; SizeX_mm: 3.2; SizeY_mm: 1.6; SizeZ_mm: 1.35; Value2: 0.25W; SizeArea_mm2: 5.12; VDC_V: 200V; AEC Category: Q200
R77 = CMP-0018061-2: RES, 200, 1%, 0.25 W, 1206; Manufacturer: Yageo America; Power_W: 250mW; TempCo: 100 ppm/C; Value_Code: 200R; U/M: EA; Value: 200; EIA_Code: E96; SizeX_mm: 3.2; SizeY_mm: 1.6; SizeZ_mm: 1.35; Value2: 0.25W; SizeArea_mm2: 5.12; VDC_V: 200V; AEC Category: Q200
R78 = CMP-0022892-5: RES, 1.80 k, 1%, 0.1 W, 0603; Manufacturer: Yageo; Power_W: 100mW; TempCo: 100 ppm/C; Value_Code: 1k80; Value: 1.80k; Res_ohm: 1.8k; SizeX_mm: 1.6; SizeY_mm: 0.8; SizeZ_mm: 1; Value2: 0.1W; SizeArea_mm2: 1.28; AEC Qualified: N; VDC_V: 75V; AEC Category: Q200; SizeAreaWB_mm2: 4.68
R79 = CMP-0023292-5: RES, 82.0 k, 1%, 0.1 W, 0603; Manufacturer: Yageo; Power_W: 100mW; TempCo: 100 ppm/C; Value_Code: 82k0; Value: 82.0k; Res_ohm: 82k; SizeX_mm: 1.6; SizeY_mm: 0.8; SizeZ_mm: 1; Value2: 0.1W; SizeArea_mm2: 1.28; AEC Qualified: N; VDC_V: 75V; AEC Category: Q200; SizeAreaWB_mm2: 4.68
R80 = CMP-0023020-5: RES, 30.0 k, 1%, 0.1 W, 0603; Manufacturer: Yageo; Power_W: 100mW; TempCo: 100 ppm/C; Value_Code: 30k0; Value: 30.0k; Res_ohm: 30k; SizeX_mm: 1.6; SizeY_mm: 0.8; SizeZ_mm: 1; Value2: 0.1W; SizeArea_mm2: 1.28; AEC Qualified: N; VDC_V: 75V; AEC Category: Q200; SizeAreaWB_mm2: 4.68
R82 = CMP-0023091-5: RES, 3.00 k, 1%, 0.1 W, 0603; Manufacturer: Yageo; Power_W: 100mW; TempCo: 100 ppm/C; Value_Code: 3k00; Value: 3.00k; Res_ohm: 3k; SizeX_mm: 1.6; SizeY_mm: 0.8; SizeZ_mm: 1; Value2: 0.1W; SizeArea_mm2: 1.28; AEC Qualified: N; VDC_V: 75V; AEC Category: Q200; SizeAreaWB_mm2: 4.68
R83 = CMP-0022895-5: RES, 1.00 k, 1%, 0.1 W, 0603; Manufacturer: Yageo; Power_W: 100mW; TempCo: 100 ppm/C; Value_Code: 1k00; Value: 1.00k; EIA_Code: E96; Res_ohm: 1k; SizeX_mm: 1.6; SizeY_mm: 0.8; SizeZ_mm: 1; Value2: 0.1W; SizeArea_mm2: 1.28; AEC Qualified: N; VDC_V: 75V; AEC Category: Q200; SizeAreaWB_mm2: 4.68
R84 R86 = CMP-0022746-5: as R8 on sheet PCB_Project_PMP41106_CoverSheet
R85 = CMP-0017847-2: RES, 10.0 k, 1%, 0.25 W, 1206; Manufacturer: Yageo America; Power_W: 250mW; TempCo: 100 ppm/C; Value_Code: 10k0; U/M: EA; Value: 10.0k; EIA_Code: E96; Res_ohm: 10k; SizeX_mm: 3.2; SizeY_mm: 1.6; SizeZ_mm: 1.35; Value2: 0.25W; SizeArea_mm2: 5.12; VDC_V: 200V; AEC Category: Q200
T2 = CMP-0120780-1: FLYBACK TRANSFORMER; Manufacturer: Bourns; Ind_H: 1.8mH; Ns1toNp: 72:35:18:15; SizeZ_mm: 14.5mm; AEC Qualified: No; Voltage_Isolation_Vrms: 3.5kV
U9 = CMP-0067241-2: 700V Flyback Switcher with Constant-Voltage Constant-Current and Primary-side Control, D0007A (SOIC-7); Alternate Manufacturer: Texas Instruments; SizeAreaWB_mm2: 55.2; U/M: EA; SizeZ_mm: 1.75; SizeX_mm: 6.0; SizeY_mm: 4.9; SizeArea_mm2: 29.4; CompType: IC; AEC Category: Q200; AEC Qualified: N

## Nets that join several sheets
5V: PCB_Project_PMP41106_BlankSheet (8 pins), PCB_Project_PMP41106_EVM_Hardware (J4.1)
10V_A: PCB_Project_PMP41106_BlankSheet (8 pins), PCB_Project_PMP41106_EVM_Hardware (C57.1 Q14.2)
IREF: PCB_Project_PMP41106_BlankSheet (5 pins), PCB_Project_PMP41106_EVM_Hardware (R85.1)
PGND: PCB_Project_PMP41106_BlankSheet (26 pins), PCB_Project_PMP41106_CoverSheet (21 pins), PCB_Project_PMP41106_EVM_Hardware (10 pins)
SGND: PCB_Project_PMP41106_BlankSheet (32 pins), PCB_Project_PMP41106_EVM_Hardware (9 pins)
VCC: PCB_Project_PMP41106_BlankSheet (R28.2), PCB_Project_PMP41106_CoverSheet (Q5.2 R4.1 R19.2 R21.2), PCB_Project_PMP41106_EVM_Hardware (R74.1)
FAN_OFF: PCB_Project_PMP41106_BlankSheet (Q9.1 R47.1 R52.2 U6.7), PCB_Project_PMP41106_EVM_Hardware (Q13.1)
FAN_ON: PCB_Project_PMP41106_BlankSheet (Q10.1 R66.2 U6.1), PCB_Project_PMP41106_EVM_Hardware (R83.2)
VBIAS: PCB_Project_PMP41106_BlankSheet (7 pins), PCB_Project_PMP41106_EVM_Hardware (R86.2)
VBUS: PCB_Project_PMP41106_BlankSheet (C14.1 C22.1 Q7.2), PCB_Project_PMP41106_CoverSheet (C11.1 D3.1 D5.1 R14.2), PCB_Project_PMP41106_EVM_Hardware (C52.1 C58.1 R76.2 T2.5)

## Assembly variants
001: not fitted J3 J4 L1 R85 R86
